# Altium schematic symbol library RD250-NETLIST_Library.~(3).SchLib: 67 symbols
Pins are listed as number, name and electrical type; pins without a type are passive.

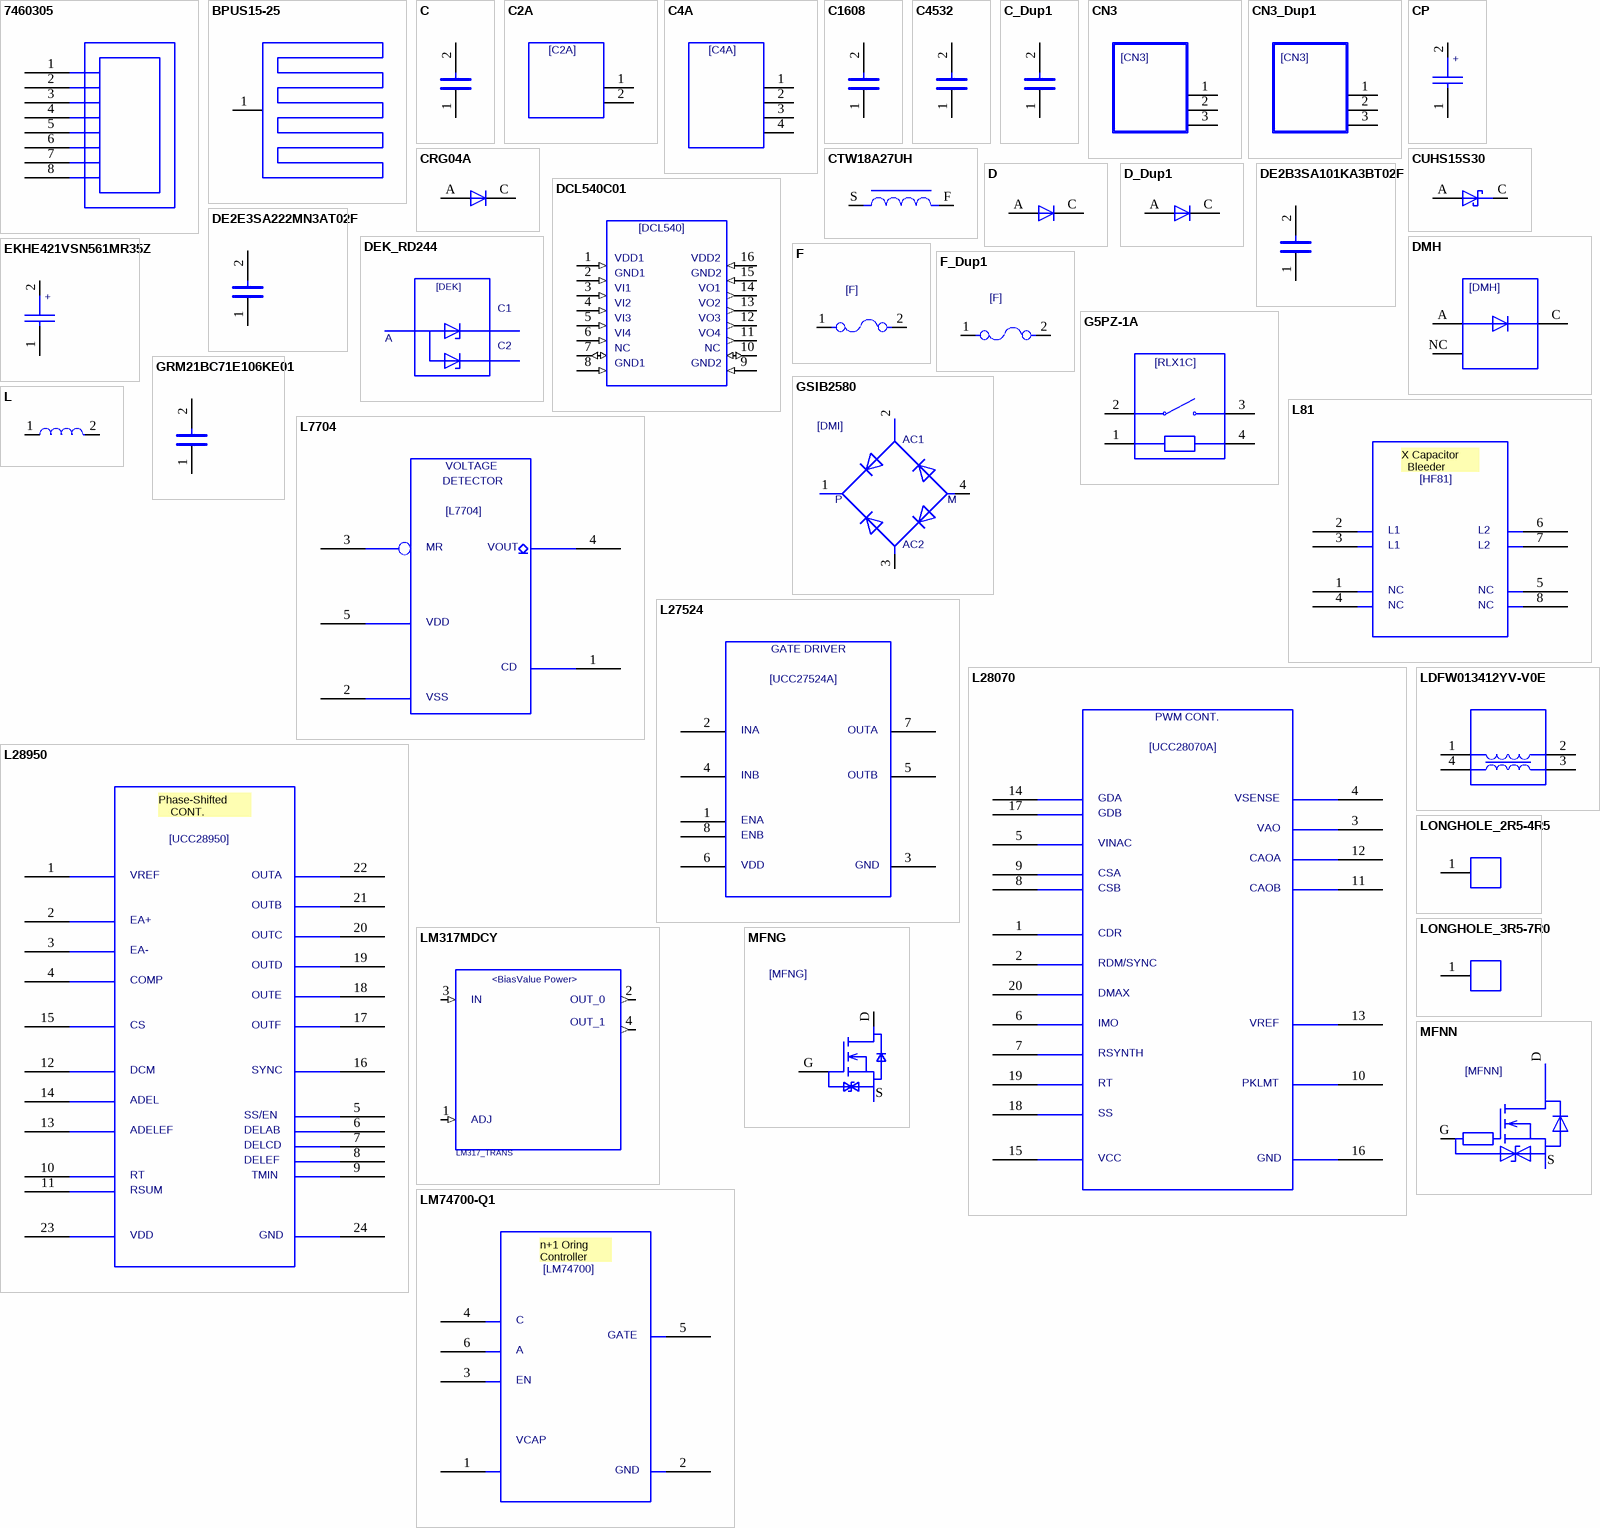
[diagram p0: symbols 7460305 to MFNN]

## 7460305
designator U?  (value not drawn)
SAVEAREA0: -4578,-286,40174,28213; SAVECOUNT: 17; TIME: 14:53:12; UPDATEUSER: t4887876; UPDATETIME: 16:00:29; VAL2: 160Amax; VAL1: M5; OriginalSymbolOrigin: (7620,27940); Altium-Right: 70; Altium-Bottom: 110
pins: 1, 2, 3, 4, 5, 6, 7, 8

## BPUS15-25
designator HS?  (value not drawn)
TIME: 14:03:26; UPDATEUSER: t4887876; UPDATETIME: 09:27:54; SAVECOUNT: 67; SAVEAREA0: -22025,-9177,43954,39124; VAL2: (!¦}}¦¦ﾑ; OriginalSymbolOrigin: (5080,22860); Altium-Right: 80; Altium-Bottom: 100
pins: 1

## C
designator U?  (value not drawn)
OriginalSymbolOrigin: (2540,7620); Altium-Right: 20; Altium-Bottom: 10
pins: 1, 2

## C2A
designator U?  (value not drawn)
SAVEAREA0: -4611,-206,24632,18258; SAVECOUNT: 25; TIME: 13:28:28; UPDATEUSER: tomizawa-y; UPDATETIME: 12:08:31; OriginalSymbolOrigin: (2540,15240); Altium-Right: 50
pins: 1, 2

## C4A
designator U?  (value not drawn)
SAVEAREA0: -8845,-265,28754,23475; SAVECOUNT: 22; TIME: 13:28:28; UPDATEUSER: tomizawa-y; UPDATETIME: 15:03:27; OriginalSymbolOrigin: (2540,20320); Altium-Right: 50; Altium-Bottom: 70
pins: 1, 2, 3, 4

## C1608
designator U?  (value not drawn)
TIME: 10:25:11; UPDATEUSER: t4887876; UPDATETIME: 06:19:09; SAVECOUNT: 10; VAL3: xx獸¦鋗ﾓ; VAL1: xxF(x); VAL2: xxV; CHIPSET: 1608; OriginalSymbolOrigin: (2540,7620); Altium-Right: 20
pins: 1, 2

## C4532
designator U?  (value not drawn)
TIME: 10:25:11; UPDATEUSER: t4887876; UPDATETIME: 06:36:44; SAVECOUNT: 15; VAL3: xx獸¦鋗ﾓ; VAL1: xxF(x); VAL2: xxV; CHIPSET: 4532; OriginalSymbolOrigin: (2540,7620); Altium-Right: 20; Altium-Bottom: 10
pins: 1, 2

## C_Dup1
designator U?, comment C  (value not drawn)
OriginalSymbolOrigin: (2540,7620); Altium-Right: 20; Altium-Bottom: 10
pins: 1, 2

## CN3
designator U?  (value not drawn)
OriginalSymbolOrigin: (2540,17780); Altium-Right: 50; Altium-Bottom: 70
pins: 1, 2, 3

## CN3_Dup1
designator U?, comment CN3  (value not drawn)
OriginalSymbolOrigin: (2540,17780); Altium-Right: 50; Altium-Bottom: 70
pins: 1, 2, 3

## CP
designator U?  (value not drawn)
SAVEAREA0: -1450,-153,20294,13055; SAVECOUNT: 52; TIME: 15:02:55; UPDATEUSER: fukuda-y; UPDATETIME: 16:13:42; OriginalSymbolOrigin: (2540,10160); Altium-Right: 20
pins: 1, 2

## CRG04A
designator U?  (value not drawn)
SAVEAREA0: -4630,-153,17114,13055; TIME: 14:49:55; UPDATEUSER: t6860224; UPDATETIME: 10:39:47; SAVECOUNT: 14; MAXV: 600V; MAXI: 1A; OriginalSymbolOrigin: (5080,5080); Altium-Right: 10; Altium-Bottom: 20
pins: A, C

## CTW18A27UH
designator U?, comment CTW18A27uH  (value not drawn)
SAVECOUNT: 9; SAVEAREA0: -384,-828,17939,11225; TIME: 16:55:46; UPDATEUSER: t4887876; UPDATETIME: 20:23:23; VAL1: 31uH; VAL2: 18A; MAKER: TAMURA; OriginalSymbolOrigin: (2540,5080); Altium-Right: 50; Altium-Bottom: 20
pins: F, S

## CUHS15S30
designator U?  (value not drawn)
SAVEAREA0: -4630,-153,17114,13055; TIME: 14:49:55; UPDATEUSER: t4887876; UPDATETIME: 17:19:09; SAVECOUNT: 10; OriginalSymbolOrigin: (5080,5080); Altium-Right: 20
pins: A, C

## D
designator U?  (value not drawn)
SAVEAREA0: -225,-91,12804,7836; SAVECOUNT: 3; TIME: 14:49:55; UPDATEUSER: 19870035; UPDATETIME: 14:20:16; OriginalSymbolOrigin: (5080,5080); Altium-Right: 10; Altium-Bottom: 20
pins: A, C

## D_Dup1
designator U?, comment D  (value not drawn)
SAVEAREA0: -225,-91,12804,7836; SAVECOUNT: 3; TIME: 14:49:55; UPDATEUSER: 19870035; UPDATETIME: 14:20:16; OriginalSymbolOrigin: (5080,5080); Altium-Right: 10; Altium-Bottom: 20
pins: A, C

## DCL540C01
designator U?  (value not drawn)
TIME: 11:12:35; UPDATEUSER: t6860224; UPDATETIME: 11:46:18; SAVECOUNT: 5; SAVEAREA0: -81052,-32740,106905,52903; OriginalSymbolOrigin: (5080,27940); Altium-Right: 80; Altium-Bottom: 110
pins: 1 (in), 2 (in), 3 (in), 4 (in), 5 (in), 6 (in), 7 (io), 8 (in), 9 (in), 10 (io), 11 (out), 12 (out), 13 (out), 14 (out), 15 (in), 16 (in)

## DE2B3SA101KA3BT02F
designator U?  (value not drawn)
VAL1: 100pF; VAL2: 250V; TIME: 18:06:52; UPDATEUSER: t6860224; SAVECOUNT: 1; OriginalSymbolOrigin: (2540,7620); Altium-Right: 20; Altium-Bottom: 10
pins: 1, 2

## DE2E3SA222MN3AT02F
designator U?  (value not drawn)
VAL1: 2.2nF(M); VAL2: 250V; TIME: 18:04:40; UPDATEUSER: t6860224; UPDATETIME: 18:05:46; SAVECOUNT: 2; OriginalSymbolOrigin: (2540,7620); Altium-Right: 20; Altium-Bottom: 10
pins: 1, 2

## DEK_RD244
designator U?  (value not drawn)
SAVEAREA0: -5273,-211,27850,20882; TIME: 14:49:55; UPDATEUSER: t6860224; UPDATETIME: 15:08:32; SAVECOUNT: 13; OriginalSymbolOrigin: (0,20320); Altium-Right: 90; Altium-Bottom: 70
pins: A, C, NC

## DMH
designator U?  (value not drawn)
SAVEAREA0: -4931,-287,27399,20979; TIME: 08:58:08; UPDATEUSER: kishi-s; UPDATETIME: 09:01:52; SAVECOUNT: 2; OriginalSymbolOrigin: (5080,17780); Altium-Right: 50; Altium-Bottom: 60
pins: A, C, NC

## EKHE421VSN561MR35Z
designator U?  (value not drawn)
SAVEAREA0: -1450,-153,20294,13055; SAVECOUNT: 55; TIME: 15:02:55; UPDATEUSER: t4887876; UPDATETIME: 15:22:11; VAL1: 560uF(M); VAL2: 420V; OriginalSymbolOrigin: (2540,10160); Altium-Right: 20
pins: 1, 2

## F
designator U?  (value not drawn)
OriginalSymbolOrigin: (2540,5080); Altium-Right: 40; Altium-Bottom: 20
pins: 1, 2

## F_Dup1
designator U?, comment F  (value not drawn)
OriginalSymbolOrigin: (2540,5080); Altium-Right: 40; Altium-Bottom: 20
pins: 1, 2

## G5PZ-1A
designator U?  (value not drawn)
SAVECOUNT: 11; SAVEAREA0: -9347,-440,34039,23986; TIME: 18:43:12; UPDATEUSER: t6860224; UPDATETIME: 18:43:42; OriginalSymbolOrigin: (5080,20320); Altium-Right: 60; Altium-Bottom: 70
pins: 1, 2, 3, 4

## GRM21BC71E106KE01
designator U?  (value not drawn)
TIME: 10:25:11; UPDATEUSER: t4887876; UPDATETIME: 16:23:00; SAVECOUNT: 11; VAL1: 10uF(K); VAL2: 25V; MAKER: Murata; CHIPSET: 2012; OriginalSymbolOrigin: (2540,7620); Altium-Right: 20; Altium-Bottom: 10
pins: 1, 2

## GSIB2580
designator U?  (value not drawn)
SAVECOUNT: 9; SAVEAREA0: -7762,-358,32649,26224; TIME: 10:09:47; UPDATEUSER: t4887876; UPDATETIME: 16:12:06; VAL1: 800V; VAL2: 25A; OriginalSymbolOrigin: (0,25400); Altium-Right: 90
pins: 1, 2, 3, 4

## L
designator U?  (value not drawn)
OriginalSymbolOrigin: (2540,5080); Altium-Right: 30; Altium-Bottom: 20
pins: 1, 2

## L81
designator U?  (value not drawn)
SAVEAREA0: -12429,-3512,55842,41521; TIME: 18:31:00; UPDATEUSER: cae; UPDATETIME: 11:10:50; SAVECOUNT: 13; OriginalSymbolOrigin: (7620,35560); Altium-Right: 110; Altium-Bottom: 130
pins: 1, 2, 3, 4, 5, 6, 7, 8

## L7704
designator U?  (value not drawn)
SAVECOUNT: 23; SAVEAREA0: -14253,-557,65080,48696; TIME: 18:10:57; UPDATEUSER: 19990028; UPDATETIME: 10:41:32; OriginalSymbolOrigin: (7620,45720); Altium-Right: 140; Altium-Bottom: 170
pins: 1, 2, 3, 4, 5

## L27524
designator U?  (value not drawn)
SAVEAREA0: -24347,-591,50370,48694; SAVECOUNT: 22; TIME: 15:02:55; UPDATEUSER: cae; UPDATETIME: 14:54:38; OriginalSymbolOrigin: (7620,45720); Altium-Right: 110; Altium-Bottom: 170
pins: 1, 2, 3, 4, 5, 6, 7, 8

## L28070
designator U?  (value not drawn)
SAVEAREA0: -12344,-1037,78634,87348; SAVECOUNT: 29; TIME: 15:02:55; UPDATEUSER: cae; UPDATETIME: 14:36:12; OriginalSymbolOrigin: (7620,83820); Altium-Right: 200; Altium-Bottom: 320
pins: 1, 2, 3, 4, 5, 6, 7, 8, 9, 10, 11, 12, 13, 14, 15, 16, 17, 18, 19, 20

## L28950
designator U?  (value not drawn)
SAVEAREA0: -25263,1478,86635,87004; SAVECOUNT: 35; TIME: 15:02:55; UPDATEUSER: cae; UPDATETIME: 16:32:09; OriginalSymbolOrigin: (7620,83820); Altium-Right: 180; Altium-Bottom: 320
pins: 1, 2, 3, 4, 5, 6, 7, 8, 9, 10, 11, 12, 13, 14, 15, 16, 17, 18, 19, 20, 21, 22, 23, 24

## LDFW013412YV-V0E
designator U?  (value not drawn)
SAVEAREA0: -19486,-4937,42112,22919; TIME: 15:15:31; UPDATEUSER: t4887876; UPDATETIME: 16:45:41; SAVECOUNT: 10; VAL1: 13.2mH; VAL2: 13A DC; OriginalSymbolOrigin: (5080,15240); Altium-Right: 50
pins: 1, 2, 3, 4

## LM317MDCY
designator U?, comment LM317_TRANS
ALTERNATE PARTNUMBER: LM317DCY; PARTNUMBER: LM317DCYR; MANUFACTURER: Texas Instruments; PIN_COUNT: 4; SYMBOLCREATER: Altium; DEVICESINPACKAGE: 1; COMP: LM317MDCY; PCB FOOTPRINT: DCY0004A_N; ISHETEROGENEOUS: False; DEVICEDESIGNATOR: A; DEVICENUMBERING: Alpha; PSPICETEMPLATE: X^@REFDES %IN %ADJ %OUT_0 %OUT_1 @MODEL; ORIGINALSYMBOLORIGIN: (2540,30480); COMPTYPE: IC; TIME: 16:40:05; UPDATEUSER: t6860224; UPDATETIME: 16:01:55; SAVECOUNT: 6; SAVEAREA0: -16909,0,49982,30480; Altium-Right: 110; Altium-Bottom: 120
simulation model LM317MDCY
pins: 1 (in), 2 (out), 3 (in), 4 (out)

## LM74700-Q1
designator U?  (value not drawn)
SAVEAREA0: -16399,-622,62276,51274; TIME: 11:49:52; UPDATEUSER: t5459927; UPDATETIME: 12:54:53; SAVECOUNT: 40; OriginalSymbolOrigin: (7620,48260); Altium-Right: 120; Altium-Bottom: 180
pins: 1, 2, 3, 4, 5, 6

## LONGHOLE_2R5-4R5
designator U?, comment Longhole_2R5-4R5  (value not drawn)
TIME: 17:17:39; UPDATEUSER: t4887876; UPDATETIME: 09:28:53; SAVECOUNT: 11; VAL3: PCB Pad; OriginalSymbolOrigin: (5080,5080); Altium-Right: 20
pins: 1

## LONGHOLE_3R5-7R0
designator U?, comment Longhole_3R5-7R0  (value not drawn)
TIME: 17:17:39; UPDATEUSER: t4887876; UPDATETIME: 09:28:53; SAVECOUNT: 12; VAL3: PCB Pad; OriginalSymbolOrigin: (5080,5080); Altium-Right: 20
pins: 1

## MFNG
designator U?  (value not drawn)
SAVECOUNT: 17; SAVEAREA0: -7084,-293,21840,15991; OriginalSymbolOrigin: (5080,12700); Altium-Right: 40; Altium-Bottom: 50
pins: D, G, S

## MFNN
designator U?  (value not drawn)
SAVECOUNT: 25; SAVEAREA0: -2884,-274,25430,18334; TIME: 08:01:03; UPDATEUSER: sato-yr; UPDATETIME: 13:42:20; OriginalSymbolOrigin: (2540,17780); Altium-Right: 80; Altium-Bottom: 70
pins: D, G, S

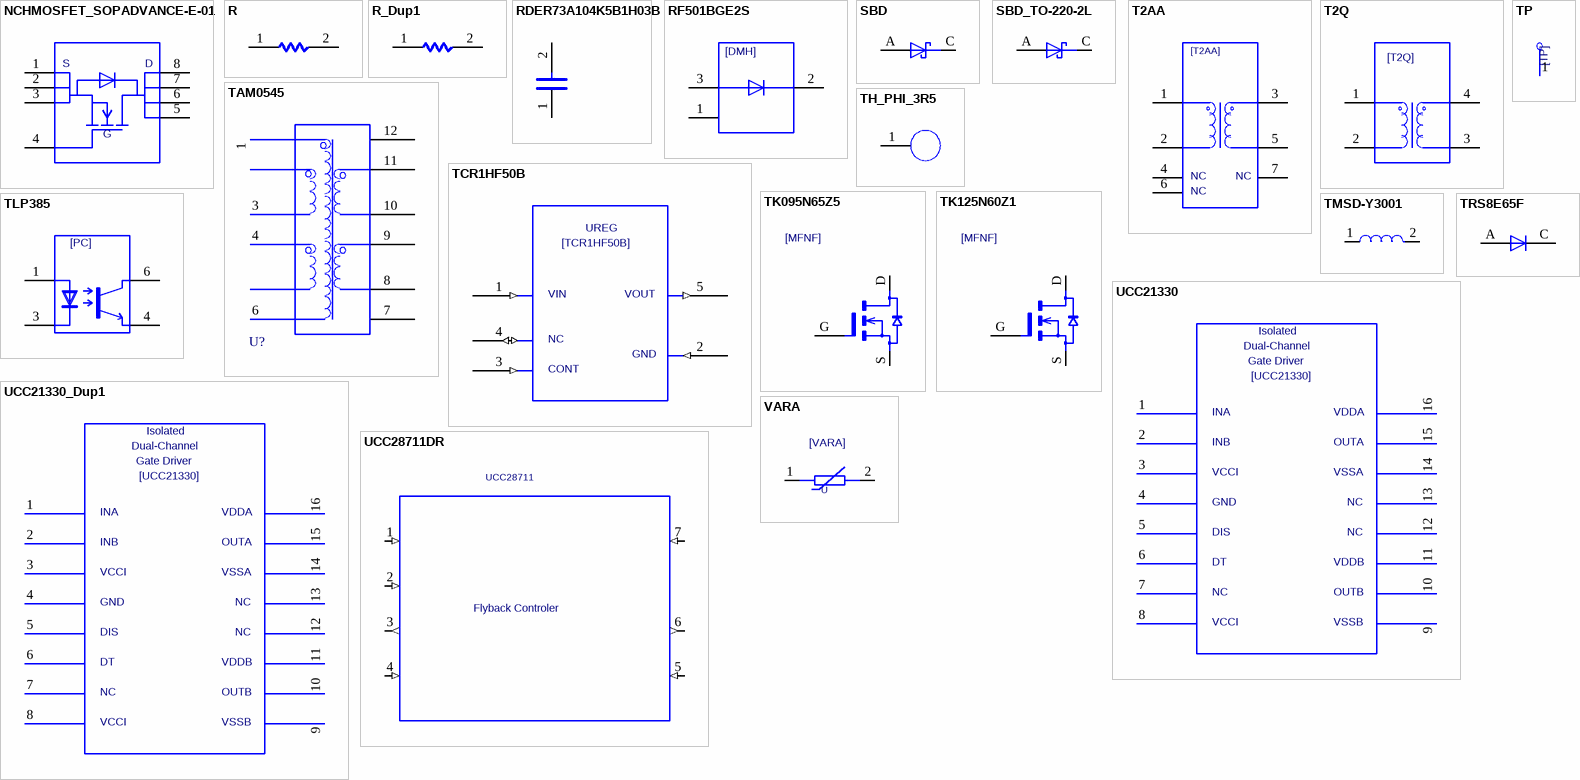
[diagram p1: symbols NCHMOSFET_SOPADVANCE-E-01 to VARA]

## NCHMOSFET_SOPADVANCE-E-01
designator U?  (value not drawn)
TIME: 18:29:30; UPDATEUSER: t4887876; UPDATETIME: 14:15:50; SAVECOUNT: 31; SAVEAREA0: -10143,-336,37609,28718; COMP: NchMOSFET_SOPAdvance(E)-01; VAL3: R獸¦#ﾐ{¦(SOPAdvance(E)); VAL1: R・&ﾟ¦#ﾐ{¦; VAL2: R・&¦#ﾐ{¦; CHIPSET: R獸¦#ﾐ{¦; OriginalSymbolOrigin: (5080,22860); Altium-Right: 70; Altium-Bottom: 80
pins: 1, 2, 3, 4, 5, 6, 7, 8

## R
designator U?  (value not drawn)
OriginalSymbolOrigin: (5080,5080); Altium-Right: 20
pins: 1, 2

## R_Dup1
designator U?, comment R  (value not drawn)
OriginalSymbolOrigin: (5080,5080); Altium-Right: 20
pins: 1, 2

## RDER73A104K5B1H03B
designator U?  (value not drawn)
VAL1: 100nF(K); VAL2: 1000VDC; TIME: 18:04:40; UPDATEUSER: t4887876; UPDATETIME: 14:18:01; SAVECOUNT: 7; OriginalSymbolOrigin: (2540,7620); Altium-Right: 20; Altium-Bottom: 10
pins: 1, 2

## RF501BGE2S
designator U?  (value not drawn)
SAVEAREA0: -4931,-287,27399,20979; TIME: 08:58:08; UPDATEUSER: t6860224; UPDATETIME: 11:55:12; SAVECOUNT: 3; OriginalSymbolOrigin: (5080,17780); Altium-Right: 50; Altium-Bottom: 60
pins: 1, 2, 3

## SBD
designator U?  (value not drawn)
SAVEAREA0: -4630,-153,17114,13055; TIME: 14:49:55; UPDATEUSER: fukuda-y; UPDATETIME: 08:16:22; SAVECOUNT: 9; OriginalSymbolOrigin: (5080,5080); Altium-Right: 20
pins: A, C

## SBD_TO-220-2L
designator U?  (value not drawn)
SAVEAREA0: -4630,-153,17114,13055; TIME: 14:49:55; UPDATEUSER: t4887876; UPDATETIME: 14:13:36; SAVECOUNT: 13; VAL1: R・&ﾟ¦#ﾐ{¦; VAL2: R・&¦#ﾐ{¦; VAL3: R獸¦#ﾐ{¦(TO-220-2L); OriginalSymbolOrigin: (5080,5080); Altium-Right: 20
pins: A, C

## T2AA
designator U?  (value not drawn)
TIME: 11:34:46; UPDATEUSER: t4887876; UPDATETIME: 16:34:34; SAVECOUNT: 11; SAVEAREA0: -20981,-344,43891,33349; OriginalSymbolOrigin: (5080,30480); Altium-Right: 50; Altium-Bottom: 110
pins: 1, 2, 3, 4, 5, 6, 7

## T2Q
designator U?  (value not drawn)
OriginalSymbolOrigin: (5080,20320); Altium-Right: 50; Altium-Bottom: 80
pins: 1, 2, 3, 4

## TAM0545
designator U?, comment T3_12V67A  (value not drawn)
UPDATEUSER: t4887876; COMP: TAM0545; UPDATETIME: 19:36:27; SAVECOUNT: 9; TIME: 16:40:06; SAVEAREA0: -9901,-21944,29587,7006; ORIGINALSYMBOLORIGIN: (-7620,0); Altium-Right: 80; Altium-Bottom: 140
pins: 1, 3, 4, 6, 7, 8, 9, 10, 11, 12

## TCR1HF50B
designator U?  (value not drawn)
SAVEAREA0: -444,-3509,43701,41525; TIME: 18:31:00; UPDATEUSER: t6860224; UPDATETIME: 12:58:25; SAVECOUNT: 16; OriginalSymbolOrigin: (7620,35560); Altium-Right: 110; Altium-Bottom: 130
pins: 1 (in), 2 (in), 3 (in), 4 (io), 5 (out)

## TH_PHI_3R5
designator U?, comment TH_phi_3R5  (value not drawn)
TIME: 17:17:39; UPDATEUSER: t4887876; UPDATETIME: 10:33:19; SAVECOUNT: 10; VAL3: PCB Pad; OriginalSymbolOrigin: (5080,5080); Altium-Right: 20
pins: 1

## TK095N65Z5
designator U?  (value not drawn)
SAVECOUNT: 12; SAVEAREA0: -7027,-292,21786,15988; TIME: 18:24:15; UPDATEUSER: t6860224; OriginalSymbolOrigin: (5080,12700); Altium-Right: 40
pins: D, G, S

## TK125N60Z1
designator U?  (value not drawn)
SAVECOUNT: 12; SAVEAREA0: -7027,-292,21786,15988; TIME: 18:23:27; UPDATEUSER: t6860224; OriginalSymbolOrigin: (5080,12700); Altium-Right: 40
pins: D, G, S

## TLP385
designator U?  (value not drawn)
TIME: 18:37:26; UPDATEUSER: t4887876; UPDATETIME: 18:41:04; SAVECOUNT: 3; VAL3: TLP385(D4BLLTL,E; OriginalSymbolOrigin: (5080,17780); Altium-Right: 50; Altium-Bottom: 70
pins: 1, 3, 4, 6

## TMSD-Y3001
designator U?  (value not drawn)
VAL1: 13uH; TIME: 11:29:15; UPDATEUSER: t4887876; UPDATETIME: 13:47:51; SAVECOUNT: 2; OriginalSymbolOrigin: (2540,5080); Altium-Right: 30; Altium-Bottom: 20
pins: 1, 2

## TP
designator U?  (value not drawn)
TIME: 16:12:21; UPDATEUSER: fukuda-y; UPDATETIME: 16:18:11; SAVECOUNT: 2; SAVEAREA0: -242,-92,12810,7836; OriginalSymbolOrigin: (0,7620); Altium-Right: 20; Altium-Bottom: 30
pins: 1

## TRS8E65F
designator U?  (value not drawn)
SAVEAREA0: -225,-91,12804,7836; SAVECOUNT: 5; TIME: 14:49:55; UPDATEUSER: t6860224; UPDATETIME: 17:57:03; VAL3: TRS8E65H; OriginalSymbolOrigin: (5080,5080); Altium-Right: 10; Altium-Bottom: 20
pins: A, C

## UCC21330
designator U?  (value not drawn)
SAVEAREA0: -23586,-777,74646,64019; SAVECOUNT: 94; TIME: 14:04:55; UPDATEUSER: t6860224; UPDATETIME: 14:44:07; OriginalSymbolOrigin: (-2540,55880); Altium-Right: 220
pins: 1, 2, 3, 4, 5, 6, 7, 8, 9, 10, 11, 12, 13, 14, 15, 16

## UCC21330_Dup1
designator U?, comment UCC21330  (value not drawn)
SAVEAREA0: -23586,-777,74646,64019; SAVECOUNT: 94; TIME: 14:04:55; UPDATEUSER: t6860224; UPDATETIME: 14:44:07; OriginalSymbolOrigin: (-2540,55880); Altium-Right: 220
pins: 1, 2, 3, 4, 5, 6, 7, 8, 9, 10, 11, 12, 13, 14, 15, 16

## UCC28711DR
designator U?, comment UCC28711
COMP: UCC28711DR; PSPICETEMPLATE: X^@REFDES %CS %VS %CBC %DRV %VDD %GND %HV @MODEL; TIME: 16:40:05; UPDATEUSER: t4887876; UPDATETIME: 09:12:44; SAVECOUNT: 14; SAVEAREA0: -40606,-13411,99691,50516; OriginalSymbolOrigin: (2540,38100); Altium-Right: 180; Altium-Bottom: 150
simulation model UCC28711DR
pins: 1 (in), 2 (in), 3 (out), 4 (in), 5 (in), 6 (out), 7 (in)

## VARA
designator U?  (value not drawn)
SAVEAREA0: -9950,-8554,25168,13619; SAVECOUNT: 12; TIME: 09:56:50; UPDATEUSER: tomizawa-y; OriginalSymbolOrigin: (2540,5080); Altium-Right: 40; Altium-Bottom: 20
pins: 1, 2

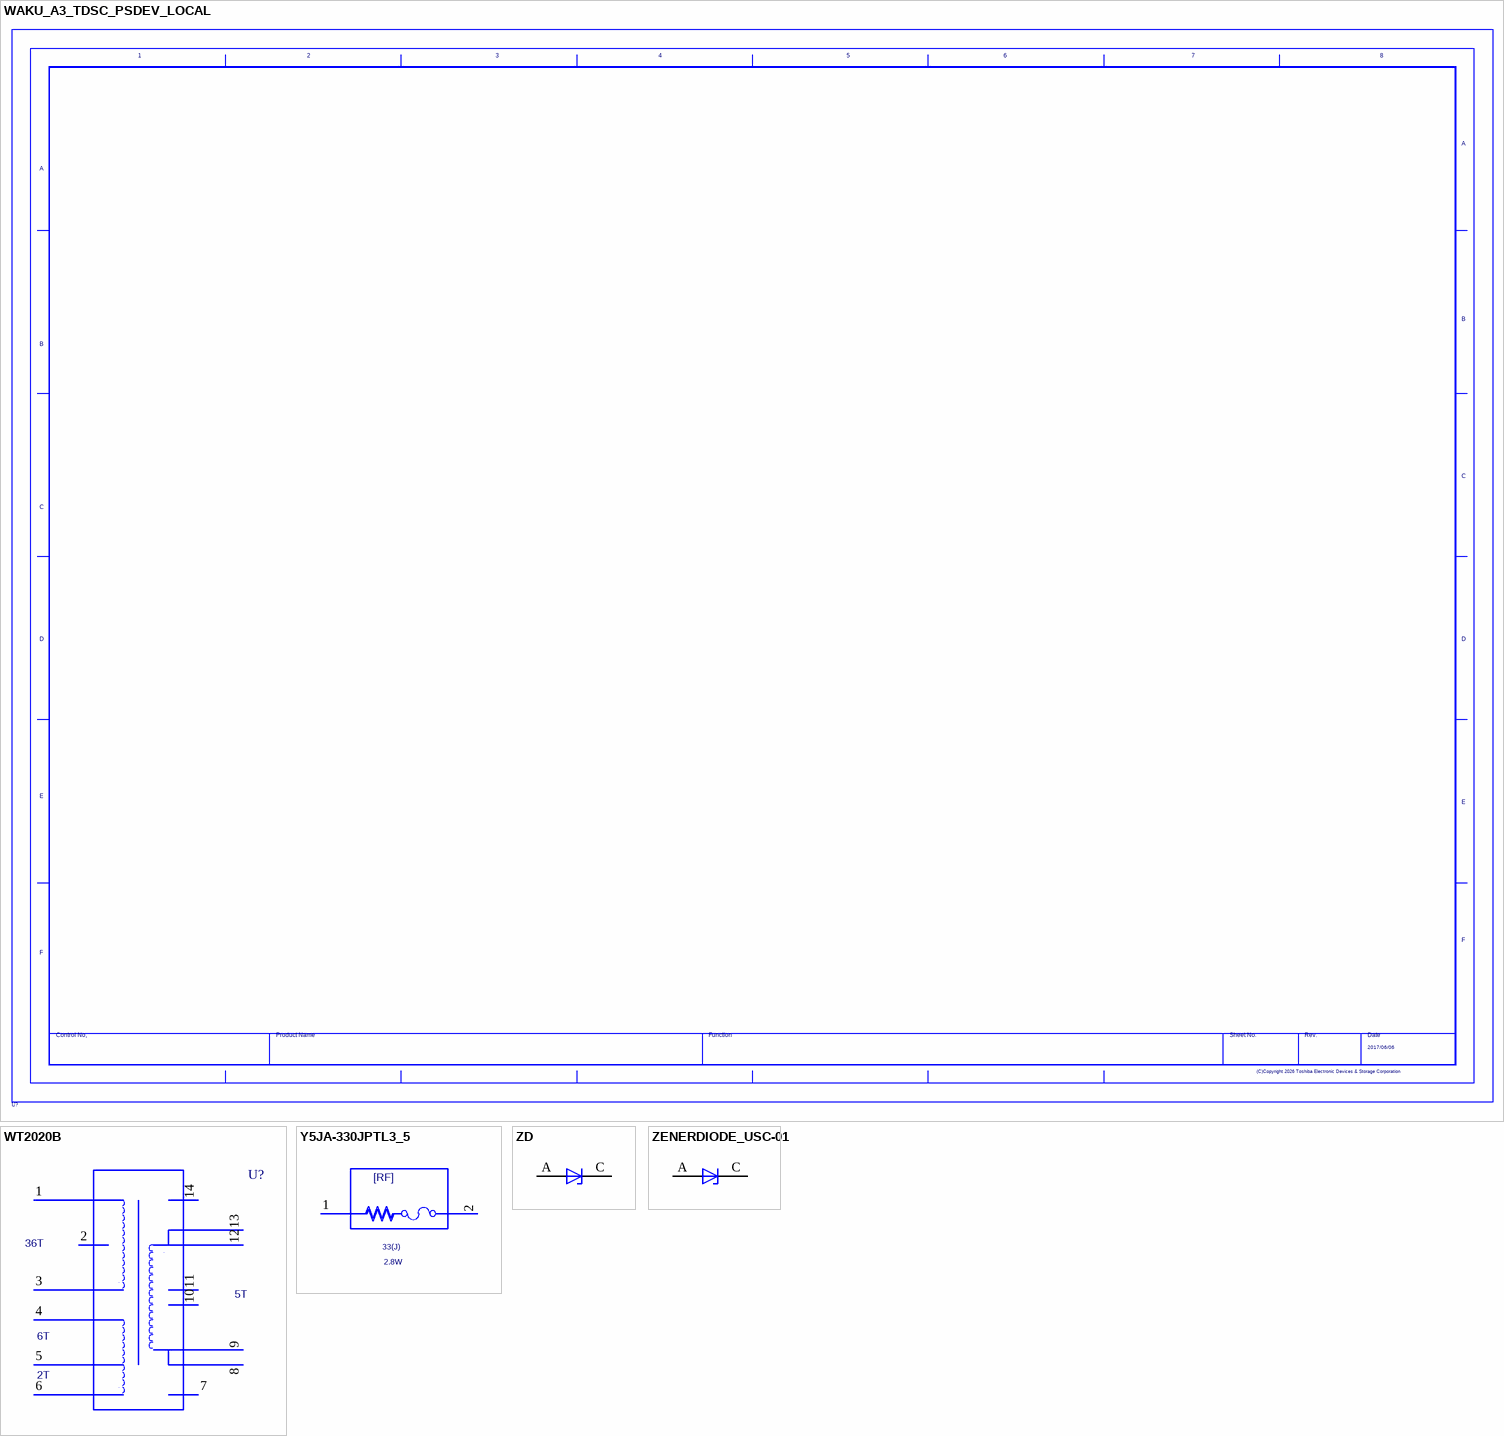
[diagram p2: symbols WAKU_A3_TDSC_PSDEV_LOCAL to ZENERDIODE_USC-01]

## WAKU_A3_TDSC_PSDEV_LOCAL
designator U?  DATE: 2017/06/06  (hidden comment: WAKU_A3_TDSC_PSDEV_LOCAL)
PLOTTIME: HH:MM; SAVEAREA0: -311037,-554865,914355,115662; TIME: 14:30:25; UPDATEUSER: t5459927; UPDATETIME: 17:16:08; SAVECOUNT: 32; ZONEOFFSETX: 36; ZONEOFFSETY: -24; OriginalSymbolOrigin: (0,434340); Altium-Right: 2360; Altium-Bottom: 1710

## WT2020B
designator U?, comment T3_12V67A  (value not drawn)
UPDATEUSER: t4887876; COMP: WT2020B; UPDATETIME: 11:02:48; SAVECOUNT: 19; TIME: 16:40:06; SAVEAREA0: -85659,-25353,110804,64166; ORIGINALSYMBOLORIGIN: (0,40640); VAL1: spec = YB-3513A; VAL2: 36:6:2:5; Altium-Right: 140; Altium-Bottom: 160
pins: 1, 2, 3, 4, 5, 6, 7, 8, 9, 10, 11, 12, 13, 14

## Y5JA-330JPTL3_5
designator U?  VAL1: 33(J)  VAL2: 2.8W  (hidden comment: Y5JA-330JPTL3_5)
VAL3: Y5JA-330JPTL3.5; TIME: 16:26:39; UPDATEUSER: t4887876; UPDATETIME: 20:40:35; SAVECOUNT: 5; OriginalSymbolOrigin: (-1270,12700); Altium-Right: 110; Altium-Bottom: 40
pins: 1, 2

## ZD
designator U?  (value not drawn)
SAVEAREA0: -4630,-153,17114,13055; TIME: 14:49:55; UPDATEUSER: fukuda-y; UPDATETIME: 08:18:42; SAVECOUNT: 6; OriginalSymbolOrigin: (5080,5080); Altium-Right: 10; Altium-Bottom: 20
pins: A, C

## ZENERDIODE_USC-01
designator U?, comment ZenerDiode_USC-01  (value not drawn)
SAVEAREA0: -4630,-153,17114,13055; TIME: 14:49:55; UPDATEUSER: t4887876; UPDATETIME: 08:23:49; SAVECOUNT: 9; OriginalSymbolOrigin: (5080,5080); Altium-Right: 10; Altium-Bottom: 20
pins: A, C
